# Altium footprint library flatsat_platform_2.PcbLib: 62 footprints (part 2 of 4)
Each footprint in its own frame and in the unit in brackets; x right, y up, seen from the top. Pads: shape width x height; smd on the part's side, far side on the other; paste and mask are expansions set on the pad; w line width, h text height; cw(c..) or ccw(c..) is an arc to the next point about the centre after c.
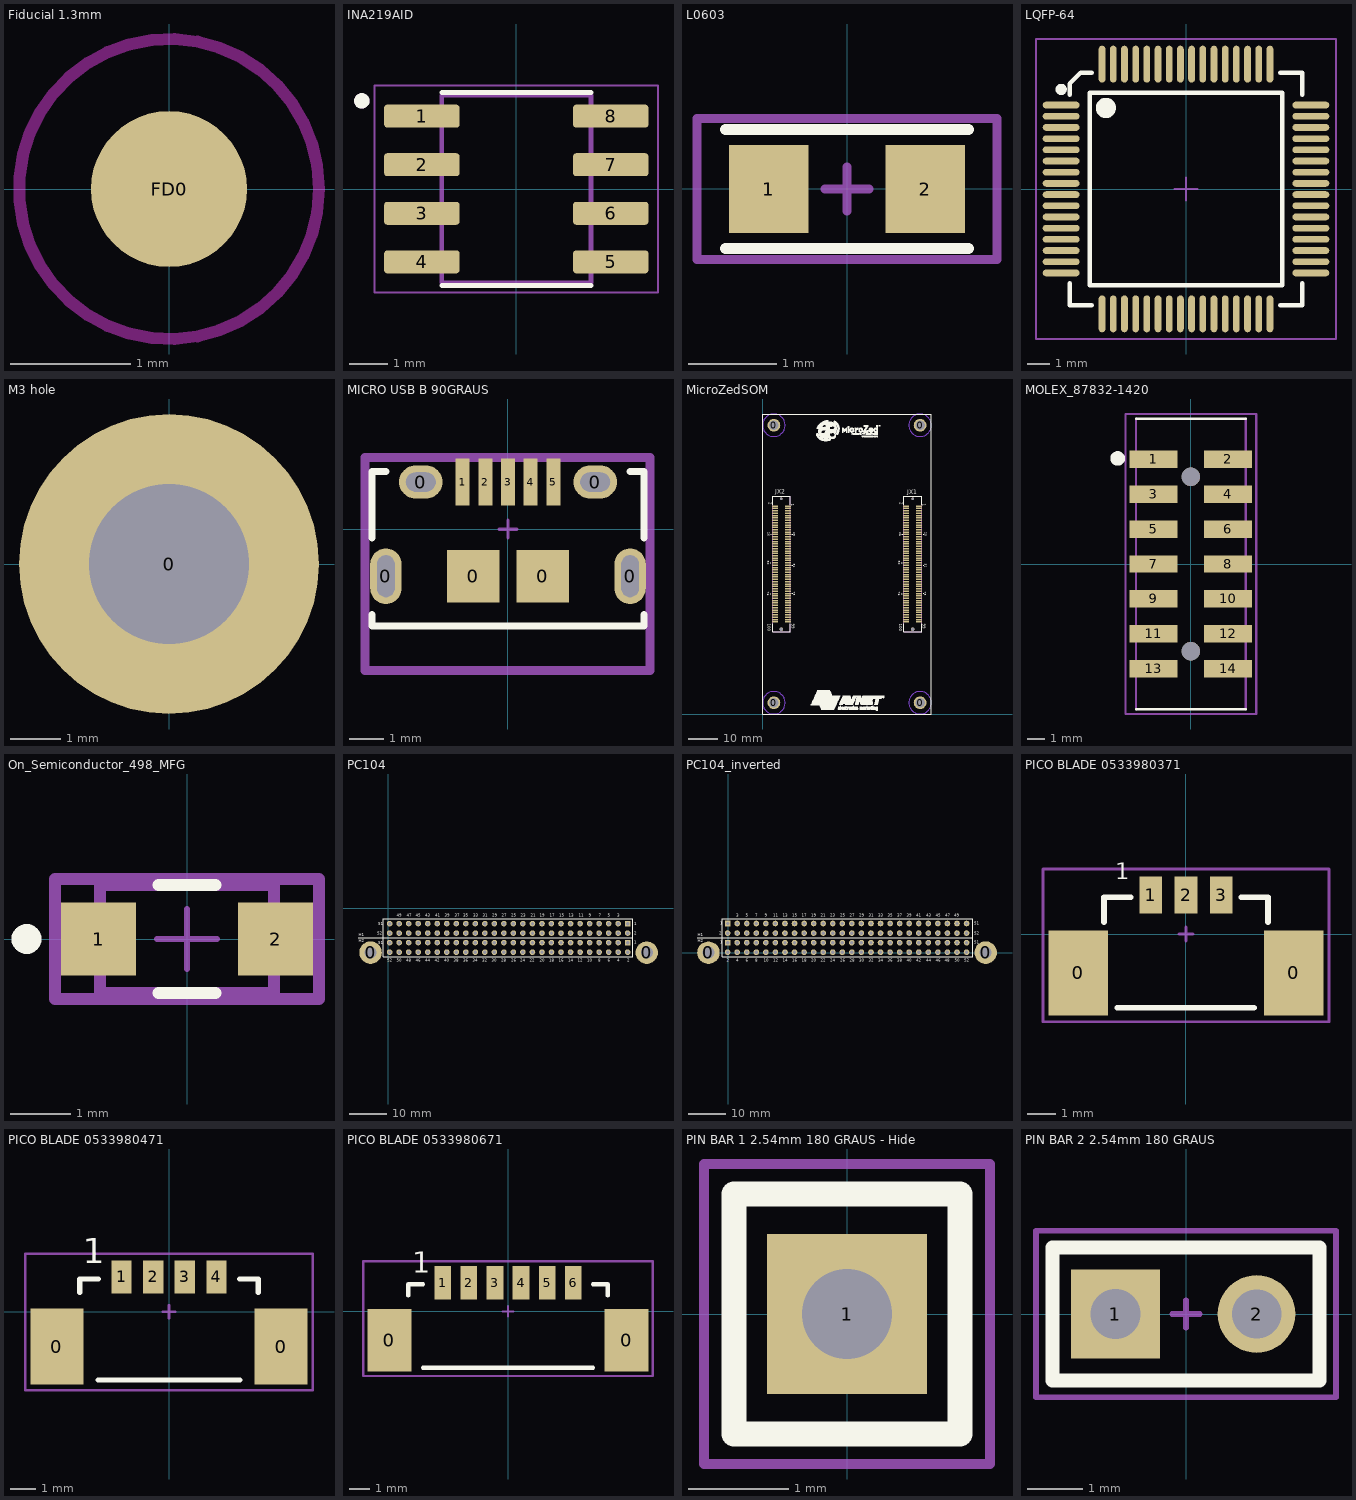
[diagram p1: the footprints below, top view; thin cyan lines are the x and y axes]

## Fiducial 1.3mm [mm]
pads (1):
  round 1.3 smd mask+0.6: FD0(0,0)
Top Layer keep-out:
  circle w0.1: c0,0 r1.25

## INA219AID [mm]
pads (8):
  rrect25% 1.97x0.6 smd: 1(-2.47,1.905) 2(-2.47,0.635) 3(-2.47,-0.635) 4(-2.47,-1.905) 5(2.47,-1.905) 6(2.47,-0.635) 7(2.47,0.635) 8(2.47,1.905)
Top Overlay:
  circle w0.2: c-4.04,2.305 r0.1
  lines w0.127: -1.95,-2.525 1.95,-2.525 ; -1.95,2.525 1.95,2.525
Mechanical 13:
  circle w0.2: c-4.04,2.305 r0.1
  lines w0.127: -1.95,-2.452 -1.95,2.452 1.95,2.452 1.95,-2.452 -1.95,-2.452
Mechanical 15:
  lines w0.05: -3.705,-2.702 -3.705,2.702 3.705,2.702 3.705,-2.702 -3.705,-2.702
3D body "step_temp.STEP": height 1.75, standoff 0, extent -2.998,-2.451 2.997,2.451

## L0603 [mm]
pads (2):
  rect 0.9x1 smd: 1(-0.889,0) 2(0.889,0)
Top Overlay:
  lines w0.127: -1.375,-0.675 1.375,-0.675 ; -1.375,0.675 1.375,0.675
Top Assembly:
  lines w0.1: -0.25,0 0.25,0 ; 0,-0.25 0,0.25 ; -1.7,-0.8 1.7,-0.8 1.7,0.8 -1.7,0.8 -1.7,-0.8
  text "'.Designator'" at -1.25,-0.5 h0.8
3D body "User Library-Chip Inductor (1).step": height 0.95, standoff 0, extent -0.8,-0.4 0.8,0.4

## LQFP-64 [mm] "64-Pin LQFP 0.5 mm Pitch"
height 1.6
pads (64):
  oval 1.65x0.3 smd: 1(-5.575,3.75) 2(-5.575,3.25) 3(-5.575,2.75) 4(-5.575,2.25) 5(-5.575,1.75) 6(-5.575,1.25) 7(-5.575,0.75) 8(-5.575,0.25) 9(-5.575,-0.25) 10(-5.575,-0.75) 11(-5.575,-1.25) 12(-5.575,-1.75) 13(-5.575,-2.25) 14(-5.575,-2.75) 15(-5.575,-3.25) 16(-5.575,-3.75) 33(5.575,-3.75) 34(5.575,-3.25) 35(5.575,-2.75) 36(5.575,-2.25) 37(5.575,-1.75) 38(5.575,-1.25) 39(5.575,-0.75) 40(5.575,-0.25) 41(5.575,0.25) 42(5.575,0.75) 43(5.575,1.25) 44(5.575,1.75) 45(5.575,2.25) 46(5.575,2.75) 47(5.575,3.25) 48(5.575,3.75)
  oval 0.3x1.65 smd: 17(-3.75,-5.575) 18(-3.25,-5.575) 19(-2.75,-5.575) 20(-2.25,-5.575) 21(-1.75,-5.575) 22(-1.25,-5.575) 23(-0.75,-5.575) 24(-0.25,-5.575) 25(0.25,-5.575) 26(0.75,-5.575) 27(1.25,-5.575) 28(1.75,-5.575) 29(2.25,-5.575) 30(2.75,-5.575) 31(3.25,-5.575) 32(3.75,-5.575) 49(3.75,5.575) 50(3.25,5.575) 51(2.75,5.575) 52(2.25,5.575) 53(1.75,5.575) 54(1.25,5.575) 55(0.75,5.575) 56(0.25,5.575) 57(-0.25,5.575) 58(-0.75,5.575) 59(-1.25,5.575) 60(-1.75,5.575) 61(-2.25,5.575) 62(-2.75,5.575) 63(-3.25,5.575) 64(-3.75,5.575)
Top Overlay:
  circle w0.6: c-3.58,3.62 r0.15
  circle w0.25: c-5.575,4.45 r0.125
  lines w0.2: -5.2,-4.2 -5.2,-5.2 ; -5.2,4.2 -5.2,4.7 -4.7,5.2 -4.2,5.2 ; -4.2,-5.2 -5.2,-5.2 ; 4.2,-5.2 5.201,-5.2 5.2,-5.201 5.2,-4.2 ; 4.2,5.2 5.2,5.2 5.2,5.2 5.2,4.2 ; -5.2,-5.2 -5.2,-5.2 ; -4.3,-4.3 4.3,-4.3 4.3,4.3 -4.3,4.3 -4.3,-4.3
Top Assembly:
  lines w0.1: -0.5,0 0.5,0 ; 0,-0.5 0,0.5 ; -6.7,-6.7 6.7,-6.7 6.7,6.7 -6.7,6.7 -6.7,-6.7
  text "'.Designator'" at -4,3 h1.2
3D body "User Library-LQFP64_Grid_0_5.STEP": height 1.6, standoff 0, extent -6,-6 6,6

## M3 hole [mm]
pads (1):
  round 6 hole 3.2: 0(0,0)

## MICRO USB B 90GRAUS [mm]
pads (11):
  oval 0.9x1.6 hole 0.5 slot 1.2 at 90 deg: 0(-3.5,-1.35) 0(3.5,-1.35)
  oval 1.25x0.95 hole 0.55 slot 0.85 at 0 deg: 0(-2.5,1.35) 0(2.5,1.35)
  rect 1.5x1.5 smd: 0(-1,-1.35) 0(1,-1.35)
  rect 0.4x1.35 smd: 1(-1.3,1.35) 2(-0.65,1.35) 3(0,1.35) 4(0.65,1.35) 5(1.3,1.35)
Top Overlay:
  lines w0.2: -3.9,-2.45 -3.9,-2.775 3.9,-2.775 3.9,-2.45 ; -3.9,-0.25 -3.9,1.65 -3.5,1.65 ; 3.5,1.65 3.9,1.65 3.9,-0.25
Top Assembly:
  lines w0.1: -0.25,0 0.25,0 ; 0,-0.25 0,0.25
  lines w0.254: -4.1,-4.05 -4.1,2.05 4.075,2.05 4.075,-4.05 -4.1,-4.05
  text "'.Designator'" at -3.4,-2.7 h1.2
3D body "User Library-10118194.STEP": height 2.73, standoff -0.55, extent -4.025,-4.03 4.025,1.55

## MicroZedSOM [mil] "MicroZed SOM Footprint"
pads (208):
  round 170 hole 125: 0(150,150) 0(150,3850) 0(2100,150) 0(2100,3850)
  round 45.98 hole 47.99 unplated: 0(250.5,1130) 0(2000.5,1130)
  round 30 hole 32.01 unplated: 0(250.5,2870) 0(2000.5,2870)
  rect 80x20 smd: JX1-1(2087.11,2771.65) JX1-2(1913.89,2771.65) JX1-3(2087.11,2740.16) JX1-4(1913.89,2740.16) JX1-5(2087.11,2708.66) JX1-6(1913.89,2708.66) JX1-7(2087.11,2677.17) JX1-8(1913.89,2677.17) JX1-9(2087.11,2645.67) JX1-10(1913.89,2645.67) JX1-11(2087.11,2614.17) JX1-12(1913.89,2614.17) JX1-13(2087.11,2582.68) JX1-14(1913.89,2582.68) JX1-15(2087.11,2551.18) JX1-16(1913.89,2551.18) JX1-17(2087.11,2519.68) JX1-18(1913.89,2519.69) JX1-19(2087.11,2488.19) JX1-20(1913.89,2488.19) JX1-21(2087.11,2456.69) JX1-22(1913.89,2456.69) JX1-23(2087.11,2425.2) JX1-24(1913.89,2425.2) JX1-25(2087.11,2393.7) JX1-26(1913.89,2393.7) JX1-27(2087.11,2362.2) JX1-28(1913.89,2362.21) JX1-29(2087.11,2330.71) JX1-30(1913.89,2330.71) JX1-31(2087.11,2299.21) JX1-32(1913.89,2299.21) JX1-33(2087.11,2267.72) JX1-34(1913.89,2267.72) JX1-35(2087.11,2236.22) JX1-36(1913.89,2236.22) JX1-37(2087.11,2204.72) JX1-38(1913.89,2204.73) JX1-39(2087.11,2173.23) JX1-40(1913.89,2173.23) JX1-41(2087.11,2141.73) JX1-42(1913.89,2141.73) JX1-43(2087.11,2110.24) JX1-44(1913.89,2110.24) JX1-45(2087.11,2078.74) JX1-46(1913.89,2078.74) JX1-47(2087.11,2047.24) JX1-48(1913.89,2047.25) JX1-49(2087.11,2015.75) JX1-50(1913.89,2015.75) JX1-51(2087.11,1984.25) JX1-52(1913.89,1984.25) JX1-53(2087.11,1952.76) JX1-54(1913.89,1952.76) JX1-55(2087.11,1921.26) JX1-56(1913.89,1921.26) JX1-57(2087.11,1889.76) JX1-58(1913.89,1889.77) JX1-59(2087.11,1858.27) JX1-60(1913.89,1858.27) JX1-61(2087.11,1826.77) JX1-62(1913.89,1826.77) JX1-63(2087.11,1795.28) JX1-64(1913.89,1795.28) JX1-65(2087.11,1763.78) JX1-66(1913.89,1763.78) JX1-67(2087.11,1732.28) JX1-68(1913.89,1732.29) JX1-69(2087.11,1700.79) JX1-70(1913.89,1700.79) JX1-71(2087.11,1669.29) JX1-72(1913.89,1669.29) JX1-73(2087.11,1637.8) JX1-74(1913.89,1637.8) JX1-75(2087.11,1606.3) JX1-76(1913.89,1606.3) JX1-77(2087.11,1574.8) JX1-78(1913.89,1574.81) JX1-79(2087.11,1543.31) JX1-80(1913.89,1543.31) JX1-81(2087.11,1511.81) JX1-82(1913.89,1511.81) JX1-83(2087.11,1480.31) JX1-84(1913.89,1480.32) JX1-85(2087.11,1448.82) JX1-86(1913.89,1448.82) JX1-87(2087.11,1417.32) JX1-88(1913.89,1417.33) JX1-89(2087.11,1385.83) JX1-90(1913.89,1385.83) JX1-91(2087.11,1354.33) JX1-92(1913.89,1354.33) JX1-93(2087.11,1322.83) JX1-94(1913.89,1322.84) JX1-95(2087.11,1291.34) JX1-96(1913.89,1291.34) JX1-97(2087.11,1259.84) JX1-98(1913.89,1259.85) JX1-99(2087.11,1228.35) JX1-100(1913.89,1228.35) JX2-1(337.11,2771.65) JX2-2(163.89,2771.65) JX2-3(337.11,2740.16) JX2-4(163.89,2740.16) JX2-5(337.11,2708.66) JX2-6(163.89,2708.66) JX2-7(337.11,2677.17) JX2-8(163.89,2677.17) JX2-9(337.11,2645.67) JX2-10(163.89,2645.67) JX2-11(337.11,2614.17) JX2-12(163.89,2614.17) JX2-13(337.11,2582.68) JX2-14(163.89,2582.68) JX2-15(337.11,2551.18) JX2-16(163.89,2551.18) JX2-17(337.11,2519.68) JX2-18(163.89,2519.69) JX2-19(337.11,2488.19) JX2-20(163.89,2488.19) JX2-21(337.11,2456.69) JX2-22(163.89,2456.69) JX2-23(337.11,2425.2) JX2-24(163.89,2425.2) JX2-25(337.11,2393.7) JX2-26(163.89,2393.7) JX2-27(337.11,2362.2) JX2-28(163.89,2362.21) JX2-29(337.11,2330.71) JX2-30(163.89,2330.71) JX2-31(337.11,2299.21) JX2-32(163.89,2299.21) JX2-33(337.11,2267.72) JX2-34(163.89,2267.72) JX2-35(337.11,2236.22) JX2-36(163.89,2236.22) JX2-37(337.11,2204.72) JX2-38(163.89,2204.73) JX2-39(337.11,2173.23) JX2-40(163.89,2173.23) JX2-41(337.11,2141.73) JX2-42(163.89,2141.73) JX2-43(337.11,2110.24) JX2-44(163.89,2110.24) JX2-45(337.11,2078.74) JX2-46(163.89,2078.74) JX2-47(337.11,2047.24) JX2-48(163.89,2047.25) JX2-49(337.11,2015.75) JX2-50(163.89,2015.75) JX2-51(337.11,1984.25) JX2-52(163.89,1984.25) JX2-53(337.11,1952.76) JX2-54(163.89,1952.76) JX2-55(337.11,1921.26) JX2-56(163.89,1921.26) JX2-57(337.11,1889.76) JX2-58(163.89,1889.77) JX2-59(337.11,1858.27) JX2-60(163.89,1858.27) JX2-61(337.11,1826.77) JX2-62(163.89,1826.77) JX2-63(337.11,1795.28) JX2-64(163.89,1795.28) JX2-65(337.11,1763.78) JX2-66(163.89,1763.78) JX2-67(337.11,1732.28) JX2-68(163.89,1732.29) JX2-69(337.11,1700.79) JX2-70(163.89,1700.79) JX2-71(337.11,1669.29) JX2-72(163.89,1669.29) JX2-73(337.11,1637.8) JX2-74(163.89,1637.8) JX2-75(337.11,1606.3) JX2-76(163.89,1606.3) JX2-77(337.11,1574.8) JX2-78(163.89,1574.81) JX2-79(337.11,1543.31) JX2-80(163.89,1543.31) JX2-81(337.11,1511.81) JX2-82(163.89,1511.81) JX2-83(337.11,1480.31) JX2-84(163.89,1480.32) JX2-85(337.11,1448.82) JX2-86(163.89,1448.82) JX2-87(337.11,1417.32) JX2-88(163.89,1417.33) JX2-89(337.11,1385.83) JX2-90(163.89,1385.83) JX2-91(337.11,1354.33) JX2-92(163.89,1354.33) JX2-93(337.11,1322.83) JX2-94(163.89,1322.84) JX2-95(337.11,1291.34) JX2-96(163.89,1291.34) JX2-97(337.11,1259.84) JX2-98(163.89,1259.85) JX2-99(337.11,1228.35) JX2-100(163.89,1228.35)
Top Layer keep-out:
  circle w4: c150,150 r150
  circle w4: c2100,3850 r150
  circle w4: c150,3850 r150
  circle w4: c2100,150 r150
Bottom Layer keep-out:
  circle w4: c150,150 r150
  circle w4: c2100,3850 r150
  circle w4: c150,3850 r150
  circle w4: c2100,150 r150
Top Overlay:
  drawing of 6871 lines, arcs and shapes, not listed
  text "JX1" at 1927,2933 h60
  text "JX2" at 170,2937 h60
  text "50" at 61.49,2041.42 h30
  text "76" at 61.49,1631.42 h30
  text "75" at 406.49,1631.42 h30
  text "51" at 411.49,2006.42 h30
  text "26" at 71.49,2421.42 h30
  text "25" at 411.49,2421.42 h30
  text "1" at 383.51,2802 h40
  text "2" at 80.51,2821 h40
  text "99" at 386.49,1201.42 h40
  text "100" at 71.49,1201.42 h40
  text "100" at 1821.49,1201.42 h40
  text "99" at 2136.49,1201.42 h40
  text "2" at 1830.51,2821 h40
  text "1" at 2133.51,2802 h40
  text "25" at 2161.49,2421.42 h30
  text "26" at 1821.49,2421.42 h30
  text "51" at 2161.49,2006.42 h30
  text "75" at 2156.49,1631.42 h30
  text "76" at 1811.49,1631.42 h30
  text "50" at 1811.49,2041.42 h30
Mechanical 13:
  lines w6: 132.39,1098.42 132.39,2901.57 368.61,2901.57 368.61,1098.42 132.39,1098.42 ; 1882.39,1098.42 2118.61,1098.42 2118.61,2901.57 1882.39,2901.57 1882.39,1098.42
3D body: height 1, standoff 0, extent -0.57,0.22 149.43,300.22
3D body: height 1, standoff 0, extent 149.43,0.22 299.43,300.22
3D body: height 1, standoff 0, extent 1949.43,3700.22 2099.43,4000.22
3D body: height 1, standoff 0, extent 2099.43,3700.22 2249.43,4000.22
3D body: height 1, standoff 0, extent 0.43,3700.22 150.43,4000.22
3D body: height 1, standoff 0, extent 150.43,3700.22 300.43,4000.22
3D body: height 1, standoff 0, extent 1950.43,0.22 2100.43,300.22
3D body: height 1, standoff 0, extent 2100.43,0.22 2250.43,300.22
3D body "s61083-101x0xxx.stp": height 183.07, standoff -27.56, extent 131.9,1099.43 368.12,2902.57
3D body "s61083-101x0xxx.stp": height 185.64, standoff -24.99, extent 1882,1097.85 2118.22,2901

## MOLEX_87832-1420 [mm]
pads (16):
  rect 2.75x1 smd: 1(-2.13,6) 2(2.13,6) 3(-2.13,4) 4(2.13,4) 5(-2.13,2) 6(2.13,2) 7(-2.13,0) 8(2.13,0) 9(-2.13,-2) 10(2.13,-2) 11(-2.13,-4) 12(2.13,-4) 13(-2.13,-6) 14(2.13,-6)
  round 1.05 hole 1.05 unplated: ""(0,-5) ""(0,5)
Top Overlay:
  circle w0.61: c-4.2,6.05 r0.11
  lines w0.127: -3.15,-8.325 3.15,-8.325 ; -3.15,8.325 3.15,8.325
Mechanical 13:
  lines w0.127: -3.15,-8.325 -3.15,8.325 ; 3.15,-8.325 3.15,8.325
Mechanical 15:
  lines w0.127: -3.75,-8.6 3.75,-8.6 3.75,8.6 -3.75,8.6 -3.75,-8.6
3D body "87832-1420.stp": height 7.61, standoff -0.99, extent -3.15,-8.268 3.15,8.382

## On_Semiconductor_498_MFG [mm]
pads (2):
  rect 1.25x1.22 smd paste+0 mask+0: 1(-1.475,0) 2(1.475,0)
Top Overlay:
  circle w0.25: c-2.675,0 r0.125
  lines w0.2: -0.475,-0.9 0.475,-0.9 ; -0.475,0.9 0.475,0.9
Mechanical 10:
  lines w0.2: -2.2,-1 -2.2,1 2.2,1 2.2,-1 -2.2,-1
  text ".Designator" at 0,-0.001 h1
Mechanical 12:
  lines w0.2: -1.45,-0.9 -1.45,0.9 1.45,0.9 1.45,-0.9 -1.45,-0.9
Mechanical 15:
  lines w0.1: -0.5,0 0.5,0 ; 0,-0.5 0,0.5
  lines w0.2: -2.2,-1 -2.2,1 2.2,1 2.2,-1 -2.2,-1
3D body "Diode_On_Semiconductor_MBR230LSFT1G_eec.STEP": height 0.25, standoff 0, extent -2.2,-1 2.2,1

## PC104 [mm] "Connector; Header; 26x4 Position"
height 3.1
pads (106):
  round 6 hole 3.2: 0(-4.686,-11.809) 0(68.998,-11.823)
  rect 1.5x1.5 hole 0.9: 1(63.906,-4.064) 53(63.906,-9.139)
  round 1.5 hole 0.9: 2(63.906,-6.604) 3(61.366,-4.064) 4(61.366,-6.604) 5(58.826,-4.064) 6(58.826,-6.604) 7(56.286,-4.064) 8(56.286,-6.604) 9(53.746,-4.064) 10(53.746,-6.604) 11(51.206,-4.064) 12(51.206,-6.604) 13(48.666,-4.064) 14(48.666,-6.604) 15(46.126,-4.064) 16(46.126,-6.604) 17(43.561,-4.064) 18(43.586,-6.604) 19(41.046,-4.064) 20(41.046,-6.604) 21(38.506,-4.064) 22(38.506,-6.604) 23(35.966,-4.064) 24(35.966,-6.604) 25(33.426,-4.064) 26(33.426,-6.604) 27(30.886,-4.064) 28(30.886,-6.604) 29(28.346,-4.064) 30(28.346,-6.604) 31(25.806,-4.064) 32(25.806,-6.604) 33(23.266,-4.064) 34(23.266,-6.604) 35(20.726,-4.064) 36(20.726,-6.604) 37(18.186,-4.064) 38(18.186,-6.604) 39(15.646,-4.064) 40(15.646,-6.604) 41(13.106,-4.064) 42(13.106,-6.604) 43(10.566,-4.064) 44(10.566,-6.604) 45(8.026,-4.064) 46(8.026,-6.604) 47(5.486,-4.064) 48(5.486,-6.604) 49(2.946,-4.064) 50(2.946,-6.604) 51(0.406,-4.064) 52(0.406,-6.604) 54(63.906,-11.684) 55(61.366,-9.144) 56(61.366,-11.684) 57(58.826,-9.144) 58(58.826,-11.684) 59(56.286,-9.144) 60(56.286,-11.684) 61(53.746,-9.139) 62(53.746,-11.684) 63(51.206,-9.139) 64(51.206,-11.684) 65(48.666,-9.144) 66(48.666,-11.684) 67(46.126,-9.144) 68(46.126,-11.684) 69(43.561,-9.144) 70(43.586,-11.684) 71(41.046,-9.144) 72(41.046,-11.684) 73(38.506,-9.144) 74(38.506,-11.684) 75(35.966,-9.144) 76(35.966,-11.684) 77(33.426,-9.144) 78(33.426,-11.684) 79(30.886,-9.144) 80(30.886,-11.684) 81(28.346,-9.144) 82(28.346,-11.684) 83(25.806,-9.144) 84(25.806,-11.684) 85(23.266,-9.144) 86(23.266,-11.684) 87(20.726,-9.144) 88(20.726,-11.684) 89(18.186,-9.144) 90(18.186,-11.684) 91(15.646,-9.144) 92(15.646,-11.684) 93(13.106,-9.144) 94(13.106,-11.684) 95(10.566,-9.144) 96(10.566,-11.684) 97(8.026,-9.144) 98(8.026,-11.684) 99(5.486,-9.144) 100(5.486,-11.684) 101(2.946,-9.144) 102(2.946,-11.684) 103(0.406,-9.144) 104(0.406,-11.684)
Top Overlay:
  lines w0.127: -8.034,-7.874 65.151,-7.874
  lines w0.254: -1.27,-12.954 -1.27,-2.794 65.278,-2.794 65.278,-12.954 -1.27,-12.954
  text "H1" at -7.874,-7.493 h0.75
  text "H2" at -7.874,-9.017 h0.75
  text "2" at 65.659,-6.985 h0.75
  text "1" at 65.659,-4.445 h0.75
  text "1" at 65.659,-9.398 h0.75
  text "2" at 63.754,-14.224 h0.75
  text "52" at -0.254,-14.224 h0.75
  text "51" at -2.667,-9.525 h0.75
  text "52" at -2.921,-6.985 h0.75
  text "51" at -2.667,-4.445 h0.75
  text "50" at 2.286,-14.224 h0.75
  text "48" at 4.826,-14.224 h0.75
  text "46" at 7.366,-14.224 h0.75
  text "44" at 9.906,-14.224 h0.75
  text "42" at 12.446,-14.224 h0.75
  text "40" at 14.986,-14.224 h0.75
  text "38" at 17.526,-14.224 h0.75
  text "36" at 20.066,-14.224 h0.75
  text "34" at 22.606,-14.224 h0.75
  text "32" at 25.146,-14.224 h0.75
  text "30" at 27.686,-14.224 h0.75
  text "28" at 30.226,-14.224 h0.75
  text "26" at 32.893,-14.224 h0.75
  text "24" at 35.306,-14.224 h0.75
  text "22" at 37.846,-14.224 h0.75
  text "20" at 40.386,-14.224 h0.75
  text "18" at 42.926,-14.224 h0.75
  text "16" at 45.466,-14.224 h0.75
  text "14" at 48.006,-14.224 h0.75
  text "12" at 50.546,-14.224 h0.75
  text "10" at 53.086,-14.224 h0.75
  text "8" at 56.007,-14.224 h0.75
  text "6" at 58.547,-14.224 h0.75
  text "4" at 61.087,-14.224 h0.75
  text "49" at 2.286,-2.286 h0.75
  text "47" at 4.953,-2.286 h0.75
  text "45" at 7.366,-2.286 h0.75
  text "43" at 9.906,-2.286 h0.75
  text "41" at 12.573,-2.286 h0.75
  text "39" at 15.113,-2.286 h0.75
  text "37" at 17.78,-2.286 h0.75
  text "35" at 20.066,-2.286 h0.75
  text "33" at 22.733,-2.286 h0.75
  text "31" at 25.273,-2.286 h0.75
  text "29" at 27.813,-2.286 h0.75
  text "27" at 30.353,-2.286 h0.75
  text "25" at 32.893,-2.286 h0.75
  text "23" at 35.433,-2.286 h0.75
  text "21" at 38.1,-2.286 h0.75
  text "19" at 40.513,-2.286 h0.75
  text "17" at 43.18,-2.286 h0.75
  text "15" at 45.593,-2.286 h0.75
  text "13" at 48.133,-2.286 h0.75
  text "11" at 50.8,-2.286 h0.75
  text "9" at 53.467,-2.286 h0.75
  text "7" at 56.134,-2.286 h0.75
  text "5" at 58.547,-2.286 h0.75
  text "3" at 61.087,-2.286 h0.75
Mechanical 15:
  text "PC104" at 49.356,-6.934 h1
3D body "SSW-126-01-G-D.stp": height 8.52, standoff -2.63, extent -1.27,-12.827 65.278,-7.874
3D body "SSW-126-01-G-D.stp": height 8.52, standoff -2.63, extent -1.27,-7.874 65.278,-2.921

## PC104_inverted [mm] "Connector; Header; 26x4 Position"
height 3.1
pads (106):
  round 6 hole 3.2: 0(-5.244,-0.012) 0(68.44,0.002)
  rect 1.5x1.5 hole 0.9: 1(-0.152,7.747) 53(-0.152,2.672)
  round 1.5 hole 0.9: 2(-0.152,5.207) 3(2.388,7.747) 4(2.388,5.207) 5(4.928,7.747) 6(4.928,5.207) 7(7.468,7.747) 8(7.468,5.207) 9(10.008,7.747) 10(10.008,5.207) 11(12.548,7.747) 12(12.548,5.207) 13(15.088,7.747) 14(15.088,5.207) 15(17.628,7.747) 16(17.628,5.207) 17(20.193,7.747) 18(20.168,5.207) 19(22.708,7.747) 20(22.708,5.207) 21(25.248,7.747) 22(25.248,5.207) 23(27.788,7.747) 24(27.788,5.207) 25(30.328,7.747) 26(30.328,5.207) 27(32.868,7.747) 28(32.868,5.207) 29(35.408,7.747) 30(35.408,5.207) 31(37.948,7.747) 32(37.948,5.207) 33(40.488,7.747) 34(40.488,5.207) 35(43.028,7.747) 36(43.028,5.207) 37(45.568,7.747) 38(45.568,5.207) 39(48.108,7.747) 40(48.108,5.207) 41(50.648,7.747) 42(50.648,5.207) 43(53.188,7.747) 44(53.188,5.207) 45(55.728,7.747) 46(55.728,5.207) 47(58.268,7.747) 48(58.268,5.207) 49(60.808,7.747) 50(60.808,5.207) 51(63.348,7.747) 52(63.348,5.207) 54(-0.152,0.127) 55(2.388,2.667) 56(2.388,0.127) 57(4.928,2.667) 58(4.928,0.127) 59(7.468,2.667) 60(7.468,0.127) 61(10.008,2.672) 62(10.008,0.127) 63(12.548,2.672) 64(12.548,0.127) 65(15.088,2.667) 66(15.088,0.127) 67(17.628,2.667) 68(17.628,0.127) 69(20.193,2.667) 70(20.168,0.127) 71(22.708,2.667) 72(22.708,0.127) 73(25.248,2.667) 74(25.248,0.127) 75(27.788,2.667) 76(27.788,0.127) 77(30.328,2.667) 78(30.328,0.127) 79(32.868,2.667) 80(32.868,0.127) 81(35.408,2.667) 82(35.408,0.127) 83(37.948,2.667) 84(37.948,0.127) 85(40.488,2.667) 86(40.488,0.127) 87(43.028,2.667) 88(43.028,0.127) 89(45.568,2.667) 90(45.568,0.127) 91(48.108,2.667) 92(48.108,0.127) 93(50.648,2.667) 94(50.648,0.127) 95(53.188,2.667) 96(53.188,0.127) 97(55.728,2.667) 98(55.728,0.127) 99(58.268,2.667) 100(58.268,0.127) 101(60.808,2.667) 102(60.808,0.127) 103(63.348,2.667) 104(63.348,0.127)
Top Overlay:
  lines w0.127: -8.288,3.937 64.897,3.937
  lines w0.254: -1.524,-1.143 65.024,-1.143 65.024,9.017 -1.524,9.017 -1.524,-1.143
  text "H2" at -8.128,2.794 h0.75
  text "H1" at -8.128,4.318 h0.75
  text "3" at 2.159,9.525 h0.75
  text "5" at 4.699,9.525 h0.75
  text "7" at 7.239,9.525 h0.75
  text "9" at 9.779,9.525 h0.75
  text "11" at 11.938,9.525 h0.75
  text "13" at 14.478,9.525 h0.75
  text "15" at 17.018,9.525 h0.75
  text "17" at 19.558,9.525 h0.75
  text "19" at 22.098,9.525 h0.75
  text "21" at 24.638,9.525 h0.75
  text "23" at 27.178,9.525 h0.75
  text "25" at 29.718,9.525 h0.75
  text "27" at 32.258,9.525 h0.75
  text "29" at 34.798,9.525 h0.75
  text "31" at 37.338,9.525 h0.75
  text "33" at 39.878,9.525 h0.75
  text "35" at 42.418,9.525 h0.75
  text "37" at 44.958,9.525 h0.75
  text "39" at 47.498,9.525 h0.75
  text "41" at 50.038,9.525 h0.75
  text "43" at 52.578,9.525 h0.75
  text "45" at 55.118,9.525 h0.75
  text "47" at 57.658,9.525 h0.75
  text "49" at 60.071,9.525 h0.75
  text "4" at 2.159,-2.413 h0.75
  text "6" at 4.699,-2.413 h0.75
  text "8" at 7.239,-2.413 h0.75
  text "10" at 9.398,-2.413 h0.75
  text "12" at 11.938,-2.413 h0.75
  text "14" at 14.478,-2.413 h0.75
  text "16" at 17.018,-2.413 h0.75
  text "18" at 19.558,-2.413 h0.75
  text "20" at 22.098,-2.413 h0.75
  text "22" at 24.638,-2.413 h0.75
  text "24" at 27.178,-2.413 h0.75
  text "26" at 29.718,-2.413 h0.75
  text "28" at 32.258,-2.413 h0.75
  text "30" at 34.798,-2.413 h0.75
  text "32" at 37.338,-2.413 h0.75
  text "34" at 39.878,-2.413 h0.75
  text "36" at 42.418,-2.413 h0.75
  text "38" at 44.958,-2.413 h0.75
  text "40" at 47.498,-2.413 h0.75
  text "42" at 50.038,-2.413 h0.75
  text "44" at 52.578,-2.413 h0.75
  text "46" at 55.118,-2.413 h0.75
  text "48" at 57.531,-2.413 h0.75
  text "50" at 60.198,-2.413 h0.75
  text "51" at 65.405,7.366 h0.75
  text "52" at 65.405,4.826 h0.75
  text "51" at 65.405,2.413 h0.75
  text "52" at 62.738,-2.413 h0.75
  text "2" at -0.381,-2.413 h0.75
  text "1" at -2.159,2.413 h0.75
  text "1" at -2.159,7.366 h0.75
  text "2" at -2.413,4.826 h0.75
Mechanical 15:
  text "PC104" at 14.398,4.877 h1
3D body "TSW-126-07-G-D.x_t": height 8.39, standoff -2.53, extent -1.27,3.937 64.77,9.017
3D body "TSW-126-07-G-D.x_t": height 8.39, standoff -2.53, extent -1.27,-1.143 64.77,3.937

## PICO BLADE 0533980371 [mm]
height 4.7
pads (5):
  rect 2.1x3 smd: 0(-3.8,-1.375) 0(3.8,-1.375)
  rect 0.8x1.3 smd: 1(-1.25,1.375) 2(0,1.375) 3(1.25,1.375)
Top Overlay:
  lines w0.2: -2.9,0.425 -2.9,1.3 -1.95,1.3 ; -2.425,-2.6 2.4,-2.6 ; 1.95,1.3 2.9,1.3 2.9,0.425
  text "1" at -2.5,1.75 h1
Top Assembly:
  lines w0.1: -0.25,0 0.25,0 ; 0,-0.25 0,0.25 ; -5.05,-3.1 5.05,-3.1 5.05,2.3 -5.05,2.3 -5.05,-3.1
  text "'.Designator'" at -4.25,-2.3 h1.2
3D body "User Library-molex 53398 white (1).step": height 4.7, standoff 0, extent -4.45,-2.5 4.45,1.7

## PICO BLADE 0533980471 [mm]
height 4.7
pads (6):
  rect 2.1x3 smd: 0(-4.425,-1.375) 0(4.425,-1.375)
  rect 0.8x1.3 smd: 1(-1.875,1.375) 2(-0.625,1.375) 3(0.625,1.375) 4(1.875,1.375)
Top Overlay:
  lines w0.2: -3.525,0.762 -3.525,1.3 -2.794,1.3 ; -2.794,-2.7 2.794,-2.7 ; 2.794,1.3 3.525,1.3 3.525,0.762
  text "1" at -3.4,1.925 h1
Top Assembly:
  lines w0.1: -0.25,0 0.25,0 ; 0,-0.25 0,0.25 ; -5.675,-3.1 5.675,-3.1 5.675,2.3 -5.675,2.3 -5.675,-3.1
  text "'.Designator'" at -2.5,0.75 h1.2
3D body "User Library-molex 53398 white (2).step": height 4.7, standoff 0, extent -5.075,-2.5 5.075,1.7
3D body "510210400_4posHousingPicoblade.stp": height 5.88, standoff 1.92, extent -3.375,-2.351 3.375,0.851

## PICO BLADE 0533980671 [mm] "CONN HEADER SMD 6POS 1.25MM"
height 4.7
pads (8):
  rect 2.1x3 smd: 0(-5.675,-1.375) 0(5.675,-1.375)
  rect 0.8x1.6 smd: 1(-3.125,1.375) 2(-1.875,1.375) 3(-0.625,1.375) 4(0.625,1.375) 5(1.875,1.375) 6(3.125,1.375)
Top Overlay:
  lines w0.2: -4.775,0.762 -4.775,1.3 -4.064,1.3 ; -4.064,-2.7 4.064,-2.7 ; 4.064,1.3 4.775,1.3 4.775,0.762
  text "1" at -4.575,1.85 h1
Top Assembly:
  lines w0.1: -0.25,0 0.25,0 ; 0,-0.25 0,0.25 ; -6.925,-3.1 6.925,-3.1 6.925,2.4 -6.925,2.4 -6.925,-3.1
  text "'.Designator'" at -3.5,0.75 h1.2
3D body "User Library-molex 53398 white (4).step": height 4.7, standoff 0, extent -6.325,-2.5 6.325,1.7
3D body "510210600_6posHousingPicoblade.stp": height 5.87, standoff 1.92, extent -4.625,-2.35 4.625,0.85

## PIN BAR 1 2.54mm 180 GRAUS - Hide [mm] "HEADER 1 2.54mm 180 GRAUS"
height 8.64
pads (1):
  rect 1.6x1.6 hole 0.9: 1(0,0)
Top Overlay:
  lines w0.254: -1.13,-1.2 -1.13,1.2 1.13,1.2 1.13,-1.2 -1.13,-1.2
Mechanical 15:
  lines w0.1: -0.25,0 0.25,0 ; 0,-0.25 0,0.25 ; -1.43,-1.5 -1.43,1.5 1.43,1.5 1.43,-1.5 -1.43,-1.5
3D body "User Library-Header_Male_1Pin.STEP": height 8.54, standoff -3, extent -1.27,-1.245 1.27,1.245

## PIN BAR 2 2.54mm 180 GRAUS [mm] "HEADER 2 2.54mm 180 GRAUS"
height 8.64
pads (2):
  rect 1.6x1.6 hole 0.9: 1(-1.27,0)
  round 1.398 hole 0.89: 2(1.27,0)
Top Overlay:
  lines w0.254: -2.4,-1.2 -2.4,1.2 2.4,1.2 2.4,-1.2 -2.4,-1.2
Mechanical 15:
  lines w0.1: -0.25,0 0.25,0 ; 0,-0.25 0,0.25 ; -2.7,-1.5 -2.7,1.5 2.7,1.5 2.7,-1.5 -2.7,-1.5
3D body "JUMPER 2 VIAS.STEP": height 8.22, standoff -3.28, extent -2.54,-1.27 2.54,1.27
